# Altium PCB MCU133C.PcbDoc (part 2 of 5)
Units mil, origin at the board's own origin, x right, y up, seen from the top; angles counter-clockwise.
Board outline 2300 x 5500 mil, 4 copper layers (Top Signal, GND, PWR, Bottom Signal), stack 61.6 mil thick; 278 components, 226 nets, 1057 pads, 868 vias.
Unrouted connection lines stored in the file: 237.
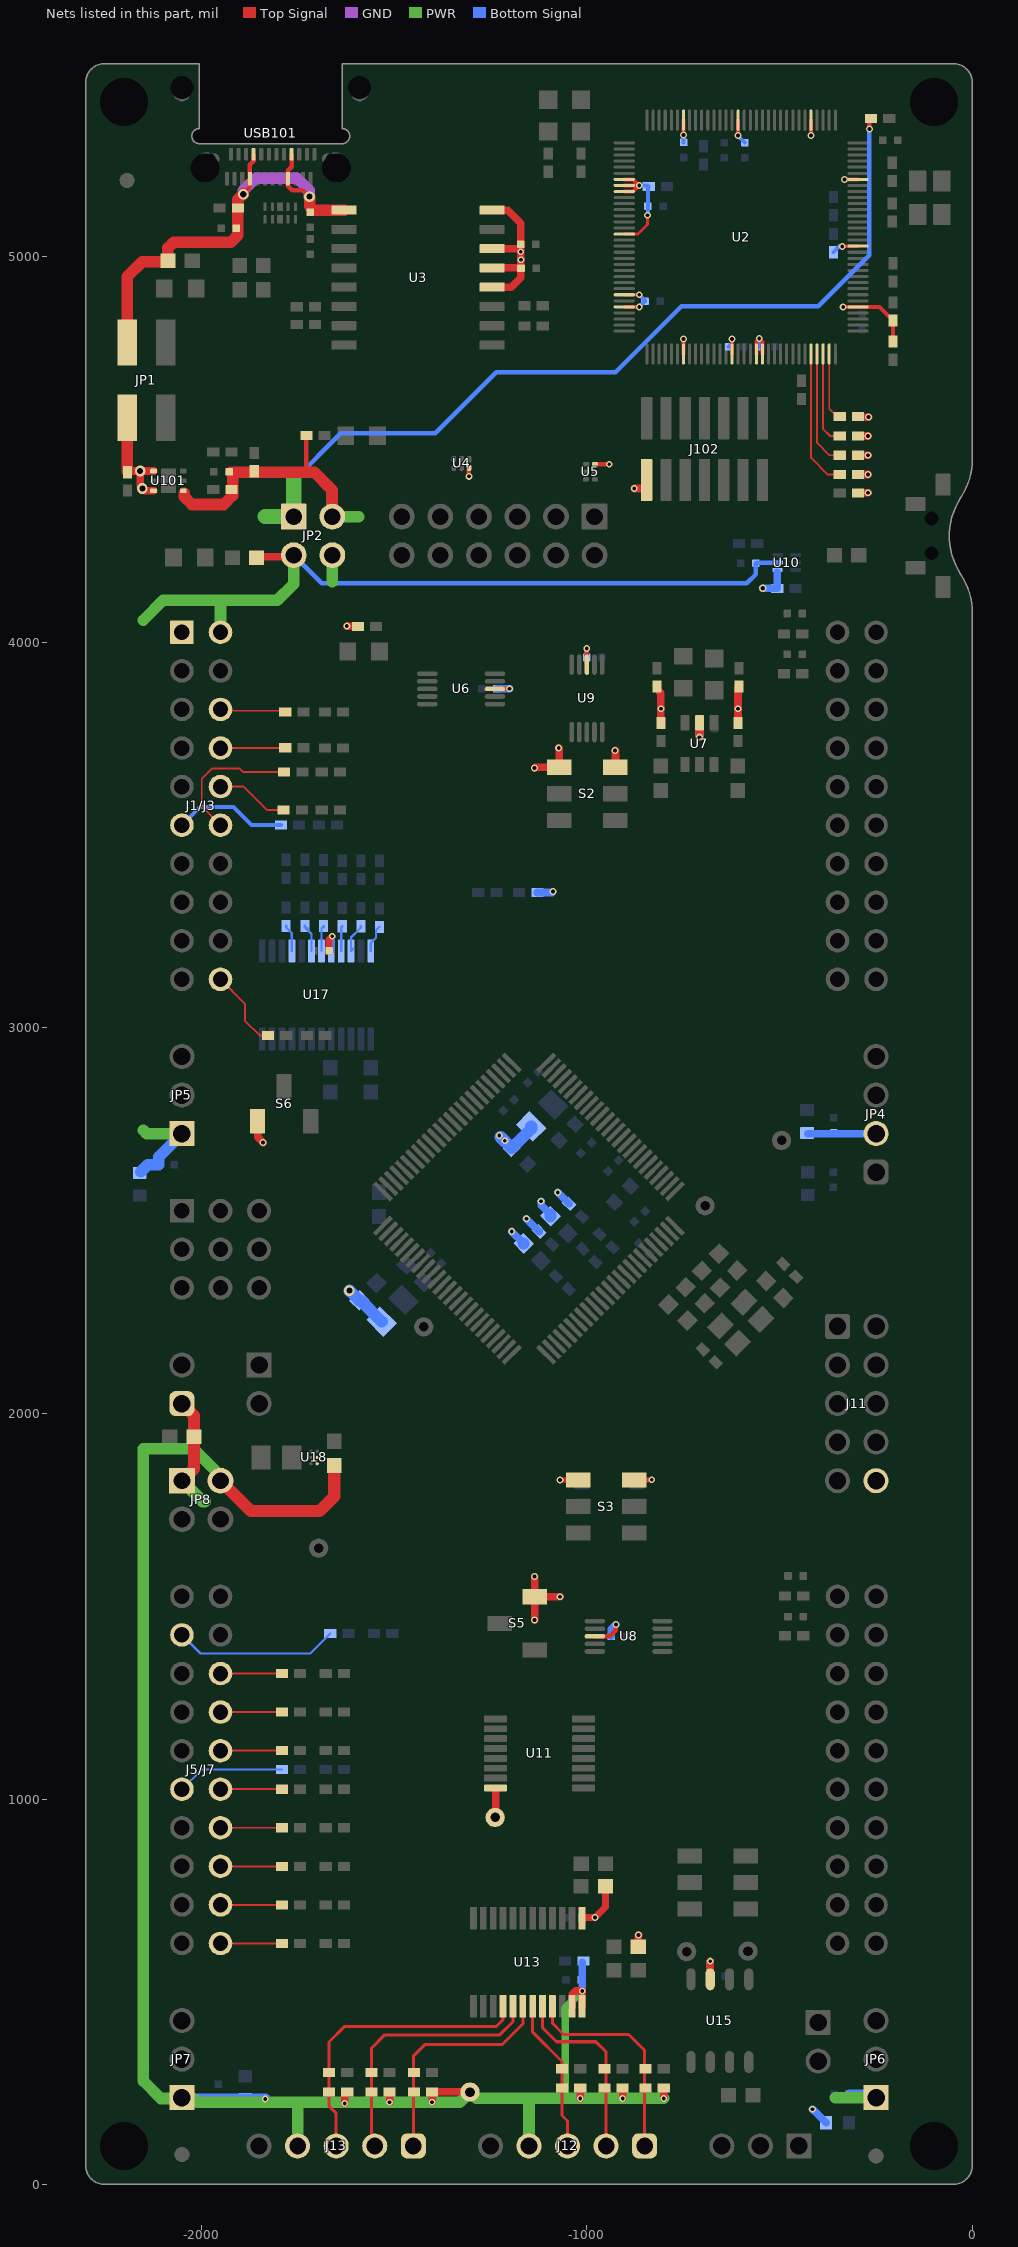
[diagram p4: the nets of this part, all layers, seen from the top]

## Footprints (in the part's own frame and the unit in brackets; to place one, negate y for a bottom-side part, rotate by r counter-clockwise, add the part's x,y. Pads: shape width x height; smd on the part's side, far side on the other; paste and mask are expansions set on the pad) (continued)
WL-SMCW_RED_0805 [mm] "SMD, 2-Leads, Body 1.6x0.8mm"
  rect 1.1x1.2 smd: 1(-1.05,0) 2(1.05,0)
  silkscreen extent -2.4,-1.1 1.5,1.1, body extent -1,-0.62 1,0.63, height 0.7
Wurth_60900213421 [mil] "Shunt, 2.54mm, Black"
  round 1 on Mech3: 0(0,0)
  body extent -98,-48 98,48, height 338
WURTH_61300211121#1 [mm] "Header, 2.54mm, 2x1, TH"
  rect 1.65x1.65 hole 1.15: 1(-1.27,0)
  round 1.65 hole 1.15: 2(1.27,0)
  silkscreen extent -2.54,-1.27 2.54,1.6, body extent -2.54,-1.27 2.54,1.27, height 8.54
WURTH_61300211121#2 [mm] "Header, 2.54mm, 2x1, TH"
  rrect50% 1.65x1.65 hole 1.15: 1(-1.27,0)
  round 1.65 hole 1.15: 2(1.27,0)
  body extent -2.54,-1.27 2.54,1.27, height 8.54
WURTH_61300311121 [mm] "Header, 2.54mm, 3x1, TH"
  rect 1.65x1.65 hole 1.15: 1(-2.54,0)
  round 1.65 hole 1.15: 2(0,0) 3(2.54,0)
  silkscreen extent -3.81,-1.65 3.81,1.27, body extent -3.81,-1.27 3.81,1.27, height 8.54
WURTH_61300411121 [mm] "Header, 2.54mm, 4x1, TH"
  rrect50% 1.65x1.65 hole 1.15: 1(-3.81,0)
  round 1.65 hole 1.15: 2(-1.27,0) 3(1.27,0) 4(3.81,0)
  body extent -5.08,-1.27 5.08,1.27, height 8.54
Wurth_61300511121 [mm] "Header, 2.54mm, 5x1, TH"
  rrect50% 1.65x1.65 hole 1.1: 1(-5.08,0)
  round 1.65 hole 1.1: 2(-2.54,0) 3(0,0) 4(2.54,0) 5(5.08,0)
  body extent -6.35,-1.27 6.35,1.27, height 8.54
WURTH_61301021121 [mm] "Header, 2.54mm, 5x2, TH"
  rrect25% 1.65x1.65 hole 1.15: 1(-5.08,-1.27)
  round 1.65 hole 1.15: 2(-5.08,1.27) 3(-2.54,-1.27) 4(-2.54,1.27) 5(0,-1.27) 6(0,1.27) 7(2.54,-1.27) 8(2.54,1.27) 9(5.08,-1.27) 10(5.08,1.27)
  silkscreen extent -6.35,-2.9 6.35,2.54, body extent -6.35,-2.54 6.35,2.54, height 8.54
YFF0006AEAE [mm] "DSBGA-6"
  round 0.23 smd paste-0.13 mask+0.038: A1(-0.2,0.4) A2(0.2,0.4) B1(-0.2,0) B2(0.2,0) C1(-0.2,-0.4) C2(0.2,-0.4)
  body extent -0.45,-0.65 0.45,0.65, height 0.63

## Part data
C1 C2 C10 C11 C12 C14 C20 C21 C22 C43 C44 C45 C46 C54 C55 C60 C64 C65 C66 C74 C81 C82 C83 C84 C105 C106: library part CMP-0090362-1, "0.1µF ±10% 10V Ceramic Capacitor X7R 0402 (1005 Metric)", Digikey Part Number=732-7513-1-ND, Manufacturer="Wurth Electronics", Mouser Part Number=710-885012205018, Operating Temperature Range="-55°C to +125°C", TempCo=15%, Temperature Characteristic=X7R, Tolerance_%=10%, ValueDisplayed=100000pF
C6 C7 C17: library part CMP-0006228-2, "CAP, CERM, 0.1 uF, 16 V, +/- 10%, X7R, 0402", Cap_Case=0402, Manufacturer="Wurth Elektronik", Supplier Part Number 1=732-7532-1-ND, TempCo=X7R, Tolerance_%=10%, Value1=Unknown, Value2=16V, ValueDisplayed=0.1uF
C9 C18 C19 C111 C113 C115 C117 C119: library part CMP-0092309-1, "Cap Ceramic 10uF 10V X5R 10% SMD 0603 85C Paper T/R", Digikey Part Number=311-1782-1-ND, Manufacturer=YAGEO, Mouser Part Number=603-CC603KRX5R6BB106, Octopart Part Number=1f0ad7d7c223c0cd, Operating Temperature Range="-55°C to +85°C", TempCo=15%, Temperature Characteristic=X5R, Tolerance_%=10%, ValueDisplayed=10uF
C15 C16 C24: library part CMP-0007091-1, "CAP, CERM, 2.2 uF, 10 V, +/- 10%, X5R, AEC-Q200 Grade 3, 0603", Cap_Case=0603, Manufacturer=TDK, Supplier Part Number 1=445-12444-1-ND, TempCo=X5R, Tolerance_%=10%, Value1=Unknown, Value2=10V, ValueDisplayed=2.2uF
C25 C26 C27 C28 C29 C30 C31 C32 C33 C34 C35 C36 C37 C38 C39 C40 C75 C76 C77 C78 C107 C108: library part CMP-0006456-2, "CAP, CERM, 330 pF, 50 V, +/- 5%, C0G/NP0, 0402", Cap_Case=0402, Manufacturer=MuRata, Supplier Part Number 1=490-1295-1-ND, TempCo=C0G/NP0, Tolerance_%=5%, Value1=Unknown, Value2=50V, ValueDisplayed=330pF
C41 C42: library part CMP-0006239-2, "CAP, CERM, 12 pF, 25 V, +/- 5%, C0G/NP0, AEC-Q200 Grade 1, 0402", Cap_Case=0402, Manufacturer=Kemet, Supplier Part Number 1=399-6829-1-ND, TempCo=C0G/NP0, Tolerance_%=5%, Value1=Unknown, Value2=25V, ValueDisplayed=12pF
C50 C51 C52 C53 C58 C102: library part CMP-0090363-1, "10000pF ±10% 25V Ceramic Capacitor X7R 0402 (1005 Metric)", Digikey Part Number=732-7545-1-ND, Manufacturer="Wurth Electronics", Mouser Part Number=710-885012205050, Operating Temperature Range="-55°C to +125°C", TempCo=15%, Temperature Characteristic=X7R, Tolerance_%=10%, ValueDisplayed=10000pF
C56 C57 C59 C61 C100 C103: library part CMP-0064924-2, "CAP, CERM, 1 uF, 10 V,+/- 20%, X5R, 0402", Cap_Case=0402, Manufacturer="Wurth Elektronik", Supplier Part Number 1=732-7489-1-ND, TempCo=X5R, Tolerance_%=20%, Value1=Unknown, Value2=10V, ValueDisplayed=1uF
C62 C63: library part CMP-0006345-2, "CAP, CERM, 12 pF, 50 V, +/- 5%, C0G/NP0, 0402", Cap_Case=0402, Manufacturer="Samsung Electro-Mechanics", Supplier Part Number 1=1276-1178-1-ND, TempCo=C0G/NP0, Tolerance_%=5%, Value1=Unknown, Value2=50V, ValueDisplayed=12pF
C67 C68 C69 C70 C71 C72 C73: library part CMP-0006231-2, "CAP, CERM, 1000 pF, 50 V, +/- 10%, X7R, 0402", Cap_Case=0402, Manufacturer="Wurth Elektronik", Supplier Part Number 1=732-7556-1-ND, TempCo=X7R, Tolerance_%=10%, Value1=Unknown, Value2=50V, ValueDisplayed=1000pF
C101: library part CMP-0092424-1, "Cap Cer 3300pF 50V X7R 0402", Digikey Part Number=732-7559-1-ND, Manufacturer="Wurth Electronics", Mouser Part Number=710-885012205064, Operating Temperature Range="-55°C to +125°C", TempCo=15%, Temperature Characteristic=X7R, Tolerance_%=10%, ValueDisplayed=3.3nF
C109: library part CMP-0006825-5, "CAP, CERM, 2.2 uF, 16 V, +/- 20%, X5R, 0603", Cap_Case=0603, Manufacturer="Wurth Elektronik", Supplier Part Number 1=732-7915-1-ND, TempCo=X5R, Tolerance_%=20%, Value1=Unknown, Value2=16V, ValueDisplayed=2.2uF
C110: library part CMP-0086225-1, "CAP, CERM, 10 µF, 16 V,+/- 10%, X5R, 0603", Cap_Case=0603, Manufacturer=MuRata, Supplier Part Number 1=490-10728-1-ND, TempCo=X5R, Tolerance_%=10%, Value2=16V, ValueDisplayed=10µF
C112 C114 C116 C118 C120 C121 C122: library part CMP-0090362-1, "0.1µF ±10% 10V Ceramic Capacitor X7R 0402 (1005 Metric)", Digikey Part Number=732-7513-1-ND, Manufacturer="Wurth Electronics", Mouser Part Number=710-885012205018, Operating Temperature Range="-55°C to +125°C", TempCo=15%, Temperature Characteristic=X7R, Tolerance_%=10%, ValueDisplayed=0.1uF
"CE Logo1": library part CMP-0074844-1
FID1 FID2 FID3 FID4 FID5 FID6: library part CMP-0077181-1, "Fiducial mark.  There is nothing to buy or mount.", Manufacturer=N/A
J1/J3: library part CMP-0003837-4, "Receptacle, 2.54mm, 10x2, Tin, TH", Alternate Manufacturer="Major League Electronics", Alternate PartNumber=CRD-081413-A-G, Manufacturer=Samtec, Supplier Part Number 1=SAM1204-10-ND
J4/J2: library part CMP-0078266-4, "Receptacle, 2.54mm, 10x2, Tin, TH", Alternate Manufacturer="Major League Electronics", Alternate PartNumber=CRD-081413-A-G, Manufacturer=Samtec, Supplier Part Number 1=SAM1204-10-ND
J5/J7: library part CMP-0081070-3, "Receptacle, 2.54mm, 10x2, Tin, TH", Alternate Manufacturer="Major League Electronics", Alternate PartNumber=CRD-081413-A-G, Manufacturer=Samtec, Supplier Part Number 1=SAM1204-10-ND
J8/J6: library part CMP-0081071-3, "Receptacle, 2.54mm, 10x2, Tin, TH", Alternate Manufacturer="Major League Electronics", Alternate PartNumber=CRD-081413-A-G, Manufacturer=Samtec, Supplier Part Number 1=SAM1204-10-ND
J10: library part CMP-0090263-1, Digikey Part Number=SAM10328-ND, Manufacturer=Samtec, Mouser Part Number=200-TSW10307GT, Operating Temperature Range="-55°C to +125°C"
J11: library part CMP-0054806-3, "Header, 2.54 mm, 5x2, Gold, TH", Current_A=3A, Manufacturer="Wurth Elektronik", Supplier Part Number 1=732-2672-ND, Voltage_V=250V
J12 J13: library part CMP-0084909-1, "Header, 2.54mm, 5x1, Gold, TH", Color=Black, Current_A=3A, Manufacturer="Wurth Elektronik", Voltage_V=250V
J14 JP5 JP6 JP7: library part CMP-0054796-1, "Header, 2.54 mm, 3x1, Gold, TH", Manufacturer="Wurth Elektronik", Supplier Part Number 1=732-5316-ND
J15 JP9: library part CMP-0054794-1, "Header, 2.54 mm, 2x1, Gold, TH", Manufacturer="Wurth Elektronik", Supplier Part Number 1=732-5315-ND
J16: library part CMP-0054794-2, "Header, 2.54 mm, 2x1, Gold, TH", Color=Black, Manufacturer="Wurth Elektronik", Supplier Part Number 1=732-5315-ND
J101: library part CMP-0092423-1, "THT Vertical Pin Header WR-PHD, Pitch 2.54 mm, Dual Row, 12 pins", Current_A=3A, Digikey Part Number=732-5297-ND, Manufacturer="Wurth Electronics", Mouser Part Number=710-61301221121, Operating Temperature Range="-40°C to +105°C", Voltage_V=250V
J102: library part CMP-0092335-1, "Connector, Header, Dual Row, 14 pin, .05\" pitch/row spacing, Male, Shrouded, Keyed, IDC, SMT", Current_A=3.4A, Digikey Part Number=612-FTSH-107-01-F-DV-K-ND, Manufacturer=Samtec, Mouser Part Number=200-FTSH10701FDVK, Octopart Part Number=b9dd70752dfc661a, Operating Temperature Range="-55°C to +125°C"
JP1: library part CMP-0055559-1, "Header, 2.54mm, 2x2, Gold, SMT", Color=Black, Manufacturer=Samtec, Supplier Part Number 1=TSM-102-01-L-DV-ND, Voltage_V=475V
JP2 JP8: library part CMP-0092422-1, "THT Vertical Pin Header WR-PHD, Pitch 2.54 mm, Dual Row, 4 pins", Current_A=3A, Digikey Part Number=732-5294-ND, Manufacturer="Wurth Electronics", Mouser Part Number=710-61300421121, Operating Temperature Range="-40°C to +105°C", Voltage_V=250V
JP4: library part CMP-0054798-2, "Header, 2.54 mm, 4x1, Gold, TH", Color=Black, Manufacturer="Wurth Elektronik", Supplier Part Number 1=732-5317-ND
L2: library part CMP-0003093-1, "Ferrite Bead, 60 ohm @ 100 MHz, 3 A, 0805", Manufacturer="Wurth Elektronik", Supplier Part Number 1=732-1612-1-ND, Value1="0.025 ohm", Value2=3A, ValueDisplayed="60 ohm"
L3: library part CMP-0003073-1, "Ferrite Bead, 220 ohm @ 100 MHz, 2 A, 0805", Manufacturer="Wurth Elektronik", Supplier Part Number 1=732-1614-1-ND, Value1="0.05 ohm", Value2=2A, ValueDisplayed="220 ohm"
L4: library part CMP-0058739-1, "Inductor, Multilayer, Ferrite, 1 uH, 0.8 A, 0.19 ohm, SMD", Manufacturer=MuRata, Supplier Part Number 1=490-4992-1-ND, Value1="0.19 ohm", Value2=0.8A, ValueDisplayed=1uH
LED0 LED1 LED4 LED6 LED7: library part CMP-0002951-3, "LED, Red, SMD", Color=Red, Manufacturer="Wurth Elektronik", Power_TotalModule=72mW, Value1=0.072W, Value2=1.9V
LED2 LED3: library part CMP-0002889-2, "LED, Blue, SMD", Color=Blue, Manufacturer=Lite-On, Value1=W, Value2=3.3V
LED5: library part CMP-0002830-3, "LED, Green, SMD", Color=green, Manufacturer=Lite-On, Value1=W, Value2=2.1V
Logo1 Logo5: library part CMP-0074838-1, "Texas Instrument Corporate Signature"
Logo3: library part CMP-0074847-1, "FCC_disclaimer"
Logo4: library part CMP-0074769-1
M1 M2 M3 M4 M5 M6 M7 M8 M9 M10 M11 M12 M13: library part CMP-0003761-2, "Shunt, 2.54mm, Gold, Black", Manufacturer="Wurth Elektronik", Supplier Part Number 1=732-2678-ND
MH1 MH2 MH3 MH4: library part CMP-0078424-2, "PCB Mounting Hole, No Pad", Manufacturer=Any, PartNumber=N/A
R1 R2 R8 R9 R12 R13 R14 R15 R16 R17 R18 R19 R20 R21 R22 R23 R24 R25 R26 R27 R44 R45 R49 R50 R84 R85 R86 R87 R103 R104 R109 R110: library part CMP-0027004-2, "RES, 0, 5%, 0.063 W, 0402", Manufacturer="Yageo America", Power_W=63mW, Supplier Part Number 1=311-0.0JRCT-ND, TempCo="200 ppm/C", Tolerance_%=5%, Value2=0.063W, Value_Code=0000, ValueDisplayed=0
R3 R28 R29 R105: library part CMP-0026962-3, "RES, 680, 5%, 0.063 W, AEC-Q200 Grade 0, 0402", Manufacturer=Vishay-Dale, Power_W=63mW, Supplier Part Number 1=541-680JCT-ND, TempCo="200 ppm/C", Tolerance_%=5%, Value2=0.063W, Value_Code=680R, ValueDisplayed=680
R5: library part CMP-0025874-4, "RES, 0, 5%, 0.1 W, AEC-Q200 Grade 0, 0603", Manufacturer=Panasonic, Power_W=100mW, Supplier Part Number 1=P0.0GCT-ND, TempCo="600 ppm/C", Tolerance_%=5%, Value2=0.1W, Value_Code=0000, ValueDisplayed=0
R7 R43: library part CMP-0025921-5, "RES, 3.0 k, 5%, 0.1 W, 0603", Manufacturer=Yageo, Power_W=100mW, Supplier Part Number 1=311-3.0KGRCT-ND, TempCo="100 ppm/C", Tolerance_%=5%, Value2=0.1W, Value_Code=3k00, ValueDisplayed=3.0k
R10 R11: library part CMP-0026890-5, "RES, 2.2 k, 5%, 0.063 W, AEC-Q200 Grade 0, 0402", Manufacturer=Vishay-Dale, Power_W=63mW, Supplier Part Number 1=541-2.2KJCT-ND, TempCo="200 ppm/C", Tolerance_%=5%, Value2=0.063W, Value_Code=2k20, ValueDisplayed=2.2k
R30 R31: library part CMP-0026826-2, "RES, 10 M, 5%, 0.063 W, AEC-Q200 Grade 0, 0402", Manufacturer=Vishay-Dale, Power_W=63mW, Supplier Part Number 1=541-10MJCT-ND, TempCo="200 ppm/C", Tolerance_%=5%, Value2=0.063W, Value_Code=10M0, ValueDisplayed=10M
R32 R33 R34 R35 R36 R37 R47 R52 R53 R107 R108: library part CMP-0025697-4, "RES, 0, 5%, 0.1 W, AEC-Q200 Grade 0, 0603", Manufacturer=Vishay-Dale, Power_W=100mW, Supplier Part Number 1=541-0.0GCT-ND, TempCo="200 ppm/C", Tolerance_%=5%, Value2=0.1W, Value_Code=0000, ValueDisplayed=0
R38 R39 R111 R112: library part CMP-0022746-5, "RES, 10.0 k, 1%, 0.1 W, 0603", Manufacturer=Yageo, Power_W=100mW, Supplier Part Number 1=311-10.0KHRCT-ND, TempCo="100 ppm/C", Tolerance_%=1%, Value2=0.1W, Value_Code=10k0, ValueDisplayed=10.0k
R48: library part CMP-0025769-4, "RES, 2.2 k, 5%, 0.1 W, AEC-Q200 Grade 0, 0603", Manufacturer=Vishay-Dale, Power_W=100mW, Supplier Part Number 1=541-2.2KGCT-ND, TempCo="200 ppm/C", Tolerance_%=5%, Value2=0.1W, Value_Code=2k20, ValueDisplayed=2.2k
R57: library part CMP-0026918-5, "RES, 3.3 k, 5%, 0.063 W, AEC-Q200 Grade 0, 0402", Manufacturer=Vishay-Dale, Power_W=63mW, Supplier Part Number 1=541-3.3KJCT-ND, TempCo="200 ppm/C", Tolerance_%=5%, Value2=0.063W, Value_Code=3k30, ValueDisplayed=3.3k
R58 R59 R60 R61 R72 R73 R74 R75 R76 R77: library part CMP-0026071-3, "RES, 1.00 k, 1%, 0.063 W, AEC-Q200 Grade 0, 0402", Manufacturer=Vishay-Dale, Power_W=63mW, Supplier Part Number 1=541-1.00KLCT-ND, TempCo="100 ppm/C", Tolerance_%=1%, Value2=0.063W, Value_Code=1k00, ValueDisplayed=1.00k
R62: library part CMP-0026824-3, "RES, 100, 5%, 0.063 W, AEC-Q200 Grade 0, 0402", Manufacturer=Vishay-Dale, Power_W=63mW, Supplier Part Number 1=541-100JCT-ND, TempCo="200 ppm/C", Tolerance_%=5%, Value2=0.063W, Value_Code=100R, ValueDisplayed=100
R63 R64: library part CMP-0026736-1, "RES, 470, 1%, 0.063 W, 0402", Manufacturer="Yageo America", Power_W=63mW, Supplier Part Number 1=311-470LRCT-ND, TempCo="100 ppm/C", Tolerance_%=1%, Value2=0.063W, Value_Code=470R, ValueDisplayed=470
R65 R67: library part CMP-0026825-5, "RES, 10 k, 5%, 0.063 W, AEC-Q200 Grade 0, 0402", Manufacturer=Vishay-Dale, Power_W=63mW, Supplier Part Number 1=541-10KJCT-ND, TempCo="200 ppm/C", Tolerance_%=5%, Value2=0.063W, Value_Code=10k0, ValueDisplayed=10k
R68: library part CMP-0026413-2, "RES, 4.87 k, 1%, 0.063 W, AEC-Q200 Grade 0, 0402", Manufacturer=Vishay-Dale, Power_W=63mW, Supplier Part Number 1=541-4.87KLCT-ND, TempCo="100 ppm/C", Tolerance_%=1%, Value2=0.063W, Value_Code=4k87, ValueDisplayed=4.87k
R70: library part CMP-0026946-3, "RES, 51, 5%, 0.063 W, AEC-Q200 Grade 0, 0402", Manufacturer=Vishay-Dale, Power_W=63mW, Supplier Part Number 1=541-51JCT-ND, TempCo="200 ppm/C", Tolerance_%=5%, Value2=0.063W, Value_Code=51R0, ValueDisplayed=51
R79: library part CMP-0022769-3, "RES, 120, 1%, 0.1 W, 0603", Manufacturer="Yageo America", Power_W=100mW, Supplier Part Number 1=311-120HRCT-ND, TempCo="200 ppm/C", Tolerance_%=1%, Value2=0.1W, Value_Code=120R
R82 R83: library part CMP-0026992-3, "RES, 0, 5%, 0.1 W, AEC-Q200 Grade 0, 0402", Manufacturer=Panasonic, Power_W=100mW, Supplier Part Number 1=P0.0JCT-ND, TempCo="600 ppm/C", Tolerance_%=5%, Value2=0.1W, Value_Code=0000, ValueDisplayed=0
R88 R89: library part CMP-0025932-5, "RES, 5.1 k, 5%, 0.1 W, 0603", Manufacturer=Yageo, Power_W=100mW, Supplier Part Number 1=311-5.1KGRCT-ND, TempCo="100 ppm/C", Tolerance_%=5%, Value2=0.1W, Value_Code=5k10, ValueDisplayed=5.1k
R100: library part CMP-0026100-2, "RES, 1.00 M, 1%, 0.063 W, AEC-Q200 Grade 0, 0402", Manufacturer=Vishay-Dale, Power_W=63mW, Supplier Part Number 1=541-1.00MLCT-ND, TempCo="100 ppm/C", Tolerance_%=1%, Value2=0.063W, Value_Code=1M00, ValueDisplayed=1.00M
R101: library part CMP-0026441-2, "RES, 52.3 k, 1%, 0.063 W, AEC-Q200 Grade 0, 0402", Manufacturer=Vishay-Dale, Power_W=63mW, Supplier Part Number 1=541-52.3KLCT-ND, TempCo="100 ppm/C", Tolerance_%=1%, Value2=0.063W, Value_Code=52k3, ValueDisplayed=52.3k
R102: library part CMP-0078244-2, "RES, 30.0 k, 1%, 0.063 W, AEC-Q200 Grade 0, 0402", Manufacturer=Vishay-Dale, Power_W=63mW, Supplier Part Number 1=541-30.0KLCT-ND, TempCo="100 ppm/C", Tolerance_%=1%, Value2=0.063W, Value_Code=30k0, ValueDisplayed=30.0k
R106: library part CMP-0023387-3, "RES, 50, 0.1%, 0.125 W, 0603", Manufacturer="Vishay Thin Film", Power_W=125mW, Supplier Part Number 1=FC0603-50BFCT-ND, TempCo="25 ppm/C", Tolerance_%=0.1%, Value2=0.125W, Value_Code=50R0, ValueDisplayed=50
S1: library part CMP-0002328-1, "Switch, SPST, 0.05 A, 12 VDC, SMD", CurrentRating_mA=50A, Manufacturer=Diptronics
S2 S3: library part CMP-0002233-1, "Switch, Dual SPDT,  2 Pos, 0.1A, 6VDC, SMD", CurrentRating_mA=100A, Manufacturer="Copal Electronics", Supplier Part Number 1=CASD20JCT-ND
S4: library part CMP-0002123-2, "SLIDE SWITCH DPDT  .1A, SMT", CurrentRating_mA=100A, Manufacturer="Copal Electronics", Supplier Part Number 1=CAS220JCT-ND
S5 S6: library part CMP-0002139-2, "Switch, Slide, SPDT  100mA, SMT", CurrentRating_mA=100A, Manufacturer="Copal Electronics", Supplier Part Number 1=CAS120JCT-ND
TP1 TP2 TP3 TP4 TP5 TP6 TP7 TP8: library part CMP-0078143-3, "TEST POINT.  No entry in BOM.", Manufacturer=N/A
U1: library part CMP-0043282-2, "Real-Time Microcontroller, LQFP100", Frequency_Fixed=150MHz, Manufacturer="Texas Instruments", Max Supply Voltage=3.63V, Min Supply Voltage=2.8V, Operating Temperature Range="-40°C to +150°C"
U2: library part CMP-0077953-1, "MSP432E401YTPDT, PDT0128A (TQFP-128)", Alternate Manufacturer="Texas Instruments", Alternate PartNumber=MSP432E401YTPDTR
U3: library part CMP-0091303-1, "Full/Low Speed Isolated USB Repeater, SOIC16-Wide", Manufacturer="Texas Instruments", Max Supply Voltage=5.5V, Min Supply Voltage=3V, Nominal Supply Current=9-9.5mA, Operating Temperature Range="-55°C to +150°C"
U4 U5: library part CMP-0043115-3, "4-Channel ESD Protection Array for High-Speed Data Interfaces, DRY0006A (USON-6)", Breakdown Voltage(Min)(V)=6, IO Capacitance(Typ)(pF)=1.6, IO Leakage Current(nA)=1, Manufacturer="Texas Instruments", Operating Temperature Range="-40 to 85 C", Rating=Catalog
U6 U8 U9: library part CMP-0067418-1, "DUAL 10-Ohm SPDT ANALOG SWITCH, DGS0010A (VSSOP-10)", Alternate Manufacturer="Texas Instruments", Alternate PartNumber=TS5A23157DGST
U7: library part CMP-0051789-2, "Dual Buffer/Driver with Open-Drain Output, DBV0006A, LARGE T&R", F @ Nom Voltage(Max)(Mhz)=150, Generic Part Number=SN74LVC2G07, ICC @ Nom Voltage(Max)(mA)=0.01, Manufacturer="Texas Instruments", Operating Temperature Range(C)="-40 to 125", Rating=Catalog, tpd @ Nom Voltage(Max)(ns)=8.6,4.4,3.7,2.9, Voltage(Nom)(V)=1.8,2.5,3.3,5
U10: library part CMP-0750051-1, "Overvoltage and Undervoltage Reset IC With Time Delay and Manual Reset, DSE0006A (WSON-6)", Alternate Manufacturer="Texas Instruments"
U11: library part CMP-0089841-1, "3 Circuit IC Switch 2:1 75Ohm 16-TSSOP", Digikey Part Number=296-3833-1-ND, Manufacturer="Texas Instruments", Max Supply Voltage=5.5V, Min Supply Voltage=2V, Mouser Part Number=595-SN74LV4053APWR, Nominal Supply Current=20uA, On State Resistance=100-225Ω, Operating Temperature Range="-40°C to +85°C"
U13: library part CMP-0121414-1, "8-Bit Dual-Supply Bus Transceiver With Configurable Voltage Translation and 3-State Outputs", Digikey Part Number=296-34079-5-ND, Manufacturer="Texas Instruments", Mouser Part Number=595-SN74LVC8T245PWR, Nominal Supply Current=25uA, Operating Temperature Range="-40°C to +85°C"
U15: library part CMP-0080978-2, "3.3-V CAN Transceivers with CAN FD (Flexible Data Rate), D0008A (SOIC-8)", Alternate Manufacturer="Texas Instruments", Alternate PartNumber=TCAN332GD
U16: library part CMP-0073613-3, "4-Channel Ultra-Low-Capacitance IEC ESD Protection Diode, DQA0010A (USON-10)", Alternate Manufacturer="Texas Instruments"
U17: library part CMP-0092155-1, "3.3-V, 2:1 (SPDT), 6-channel analog multiplexer with 1.8-V compatible control inputs 24-TSSOP -40 to 85", Digikey Part Number=296-24570-1-ND, Manufacturer="Texas Instruments", Max Supply Voltage=3.6V, Min Supply Voltage=1.65V, Mouser Part Number=595-TS3A27518EPWR, Nominal Supply Current=0.01-0.04uA, Octopart Part Number=cf0206a9c1b910c5, On State Resistance=4.4Ω, Operating Temperature Range="-40°C to +85°C"
U18: library part CMP-0067212-2, "5V, 500mA, 4MHz Step-Up DC/DC Converter, YFF0006AEAE (DSBGA-6)", Alternate Manufacturer="Texas Instruments", Alternate PartNumber=TPS61241YFFT, Operating Temperature Range="-40 to 85 C", Rating=Catalog
U101: library part CMP-0066914-5, "1% High-Accuracy, 1-A, Low-Dropout Regulator with Reverse Current Protection, DRV0006A (WSON-6)", Alternate Manufacturer="Texas Instruments", Alternate PartNumber=TPS7A3701DRVT
USB101: library part CMP-0092137-1, "Connector, USB Type-C 24 pin Mid Mount dual row Receptacle Surface Mount", Manufacturer=MUP, Operating Temperature Range="-25°C to +85°C"
Y1: library part CMP-0094478-1, "Crystal 16 MHz ±20ppm Crystal 8pF 70 Ohms 4-SMD, No Lead", Digikey Part Number=732-830064296CT-ND, Frequency Stability=20ppm, Frequency_Fixed=16MHz, Load Capacitance=8pF, Manufacturer=Wurth, Mouser Part Number=710-830064296, Operating Temperature Range="-10°C to +70°C"
Y2: library part CMP-0093781-1, "20 MHz ±10ppm Crystal 8pF 50 Ohms 4-SMD, No Lead", Digikey Part Number=1923-830108207209CT-ND, Frequency Stability=20ppm, Frequency Tolerance=10ppm, Frequency_Fixed=20MHz, Load Capacitance=8pF, Manufacturer="Wurth Electronics", Mouser Part Number=710-830108207209, Operating Temperature Range="-40°C to +85°C"
ZZ1: library part CMP-0077236-1
ZZ2: library part CMP-0077237-1
ZZ3: library part CMP-0077238-1

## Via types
v1: diameter 17.72, hole 9.84, Top Signal to Bottom Signal, tented both sides, 822 vias
v2: diameter 19.68, hole 11.81, Top Signal to Bottom Signal, tented both sides, 22 vias
v3: diameter 27.56, hole 15.75, Top Signal to Bottom Signal, tented both sides, 17 vias
v4: diameter 15.75, hole 7.87, Top Signal to Bottom Signal, tented both sides, 5 vias
v5: diameter 19.68, hole 7.87, Top Signal to Bottom Signal, tented both sides, 2 vias

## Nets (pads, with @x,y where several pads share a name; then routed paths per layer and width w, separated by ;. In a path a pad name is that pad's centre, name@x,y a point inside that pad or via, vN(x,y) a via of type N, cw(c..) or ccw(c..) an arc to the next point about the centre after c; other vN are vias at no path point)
+3V3_MCU: C6.1 C16.1 C18.2 C43.1 C44.2 C45.1 C46.2 C64.1 C74.1 C109.1 C113.2 C114.1 C117.2 C118.1 C121.1 J1/J3.1 J11.10 J16.1 JP2.4 JP4.2 JP6.1 JP8.1 L2.1 L3.1 R3.2 R10.2 R11.2 R28.2 R29.2 R30.2 R31.2 R47.2 R48.2 R82.1 R111.2 R112.2 S2.1 S2.4 S3.3 S3.6 S5.3 S6.1 TP4.1 U6.8 U7.5 U8.8 U9.8 U10.1 U11.16 U13.1 U15.3 U17.8 | length 2760.9
  Top Signal w11.81: U6.8@-1238.35,3878.86 -1237.87,3879.33 v1(-1200.35,3879.33) ; v1(-1069.44,1827.4) S3.6@-1022.6,1827.4 ; U9.8@-1000.39,3946.42 v1(-1000.39,3983.94) ; U9.8@-999.93,3941.88 -999.93,3969.47 ; U8.8@-979.15,1422.07 -940.42,1422.07 -924.74,1437.75 v1(-924.74,1452.3) ; S3.3@-876.93,1827.4 -832.21,1827.4 v1(-831.74,1827.87)
  Top Signal w17.72: C121.1@-1668.53,3199.32 -1668.53,3229.06 v1(-1660.04,3237.55) ; U13.1@-1012.56,692.99 v1(-978.89,692.99) -951.93,719.96 R47.2@-951.93,774.29
  Top Signal w19.68: S6.1@-1853.94,2758.01 -1853.94,2716.85 v1(-1839.51,2702.42) ; JP2.4@-1660.04,4225.55 JP2.4@-1658.78,4224.29 ; v1(-1622.4,4041.57) R3.2@-1599.37,4041.57 ; TP4.1@-1237.05,975.35 -1236.75,975.65 U11.16@-1236.75,1020.87 ; v1(-1135.52,3673.55) -1133.52,3675.55 S2.1@-1072.03,3675.55 ; v1(-1135.43,1464.3) S5.3@-1135.43,1524.5 ; v1@-1135.43,1576.57 S5.3@-1135.43,1524.5 ; v1(-1073.11,3725.55) -1071.81,3724.25 S2.1@-1071.81,3675.77 ; v1@-1069.21,1524.5 S5.3@-1135.43,1524.5 ; v1(-926.77,3719.42) -925.67,3718.32 S2.4@-925.67,3676.24 ; R48.2@-866.79,616.5 -866.79,646.79 v1(-866.1,647.48) ; R28.2@-819.25,3879.41 -808,3868.16 R30.2@-808,3790.7 ; v1(-708,3753.69) U7.5@-708,3791.21 ; U15.3@-680.16,532.64 U15.3@-680.04,532.52 ; U15.3@-679.93,532.86 v1(-679.93,579.2) ; R31.2@-608,3790.7 R29.2@-608,3883.7
  Top Signal w31.5: JP8.1@-2050.04,1825.55 -2018.7,1856.89 C109.1@-2018.7,1939.12 -2018.7,1994.21 J16.1@-2050.04,2025.55
  PWR w30: -1660.04,4157.24 JP2.4@-1660.04,4225.55 ; -355.91,225.55 JP6.1@-250.04,225.55
  PWR w31.5: JP8.1@-2050.04,1825.55 -1995.94,1771.46 -1990.85,1771.46
  Bottom Signal w10: U17.8@-1663.73,3200.43 U17.8@-1662.62,3199.32 ; v1@-1660.04,3237.35 v1(-1660.04,3237.55)
  Bottom Signal w11.81: v1(-1000.39,3983.94) -1000.28,3983.82 C46.2@-1000.28,3960.28
  Bottom Signal w17.72: U17.8@-1662.62,3199.32 -1662.62,3234.77 v1@-1660.04,3237.35 ; C64.1@-1011.81,692.05 -979.84,692.05 v1(-978.89,692.99)
  Bottom Signal w19.68: C43.1@-1233.7,3879.33 v1(-1200.35,3879.33) ; v1(-1194.66,2471.7) R112.2@-1163.88,2440.91 ; v1(-1156.83,2504.65) R10.2@-1123.9,2471.7 ; R11.2@-1128.35,3350.95 -1090.43,3350.95 v1(-1088.15,3353.24) ; v1(-1118.68,2550.27) -1118.68,2540.31 R111.2@-1094.02,2515.66 ; v1(-1075.63,2573.19) -1075.53,2573.19 R82.1@-1045.97,2543.63 ; C45.1@-936.46,1422.07 -936.46,1440.58 v1(-924.74,1452.3) ; v1(-708,3753.69) C44.2@-708,3774.77 ; v1(-679.93,579.2) -679.72,578.99 C74.1@-679.72,540.88 ; v2(-544.29,4139.55) C6.1@-506.38,4139.55 ; C6.1@-506.15,4139.78 -506.15,4181.55 ; C113.2@-427.07,2725.55 JP4.2@-250.04,2725.55 JP4.2@-255.04,2720.55 ; v1(-415,195.73) -414.74,195.73 C117.2@-379.57,160.55
  Bottom Signal w23.62: C118.1@-319.33,234.55 -259.04,234.55 JP6.1@-250.04,225.55
  Bottom Signal w31.5: v3@-1615.11,2318.22 C16.1@-1590.15,2293.26 -1587.23,2293.26 L2.1@-1531.95,2237.98 ; v1@-1223.68,2716.97 C18.2@-1194.66,2687.96 -1144.32,2738.3 L3.1@-1144.32,2744.27 ; R112.2@-1163.88,2440.47 R112.2@-1163.88,2440.91 ; R111.2@-1094.02,2511.48 R111.2@-1094.02,2515.66
  other v1: -1069.44,1524.5 -1135.83,1577.36 -1212.7,2707.18 -1227.32,2720.65 -808.11,3827.42 -608.11,3827.42
  other v3: -1616.04,2318.55
+3V3_XDS110: C1.2 C2.2 C51.2 C52.2 C53.2 C54.2 C55.2 C56.1 C57.1 C58.2 C102.2 C103.1 J102.1 JP2.3 R57.2 R58.2 R59.2 R60.2 R61.2 R65.2 R70.2 R101.2 R105.2 U2.7 U2.8 U2.9 U2.16 U2.26 U2.28 U2.39 U2.47 U2.51 U2.52 U2.69 U2.79 U2.90 U2.101 U2.113 U2.122 U3.12 U3.13 U3.14 U3.16 U4.6 U5.6 U101.1 | length 2627.8
  Top Signal w7.87: U2.16@-902.99,5058.43 -867.56,5058.43 -842.64,5083.35 v1(-842.64,5107.2)
  Top Signal w10: U2.28@-902.99,4869.45 v1(-864.33,4869.45) ; U2.26@-902.99,4900.94 v1(-864.33,4900.94) ; U2.9@-902.99,5168.66 -880.08,5168.66 v1(-864.33,5184.41) ; U2.8@-902.99,5184.41 v1(-864.33,5184.41) ; U2.7@-902.99,5200.16 -880.08,5200.16 v1(-864.33,5184.41) ; U2.39@-749.45,4747.4 v1(-749.45,4786.06) ; v1(-749.45,5315.04) U2.122@-749.45,5353.7 ; U2.47@-623.46,4747.4 v1(-623.46,4786.06) ; v1(-607.72,5313.77) U2.113@-607.72,5353.7 ; U2.51@-560.47,4747.4 -560.47,4779.57 v1(-552.83,4787.2) -544.72,4779.09 U2.52@-544.72,4747.4 ; v1(-418.74,5313.77) U2.101@-418.74,5353.7 ; v1@-336.73,5026.65 U2.79@-296.46,5026.65 ; v1(-335.35,4869.45) U2.69@-296.69,4869.45 -241.46,4869.45 R65.2@-206.02,4834.02 ; v1(-331.77,5200.16) U2.90@-296.69,5200.16 ; R70.2@-206.38,4779.76 -206.38,4833.66 R65.2@-206.02,4834.02 ; R65.2@-203.35,4836.69 R65.2@-206.02,4834.02
  Top Signal w11.81: -1727.28,4445.79 R105.2@-1727.28,4535.55 ; v1(-1305.75,4430.04) -1305.75,4451.46 U4.6@-1305.28,4451.93 ; U5.6@-979.13,4461.42 v1(-942.07,4461.42)
  Top Signal w19.68: U3.12@-1245.67,4920.55 -1195.55,4920.55 -1171.46,4944.65 C2.2@-1171.46,4970.55 ; U3.13@-1245.67,4970.55 C2.2@-1171.46,4970.55 ; U3.14@-1245.67,5020.55 v1@-1174.8,5020.55 ; U3.16@-1245.67,5120.55 -1205.31,5120.55 -1171.46,5086.69 -1171.46,5021.38 -1171.46,4997.17 C2.2@-1171.46,4970.55 ; C2.2@-1170.71,4969.92 -1171.34,4970.55 C2.2@-1171.46,4970.55 ; v1(-876.93,4398.44) -851.99,4398.44 -844.84,4405.59 J102.1@-844.84,4420.43
  Top Signal w20: R57.2@-297.13,4387.48 R57.2@-296.97,4387.32 v1(-270.79,4387.32) ; R61.2@-297.13,4434.72 v1(-270.94,4434.72) ; R60.2@-297.13,4484.72 v1(-270.94,4484.72) ; R59.2@-297.13,4534.72 v1(-270.94,4534.72) ; R58.2@-295.98,4583.58 v1(-269.8,4583.58)
  Top Signal w30: -2044.37,4386.42 -2044.37,4377.44 -2023.98,4357.05 -1941.93,4357.05 -1918.82,4380.16 C102.2@-1918.82,4440.63 ; C102.2@-1922.99,4441.18 -1707.01,4441.18 -1660.04,4394.21 JP2.3@-1660.04,4325.55
  PWR w30: JP2.3@-1660.04,4311.34 JP2.3@-1660.04,4325.55 ; -1660.04,4387.64 JP2.3@-1660.04,4325.55 ; -1591.93,4325.55 JP2.3@-1660.04,4325.55
  Bottom Signal w10: v1(-864.33,4869.45) -850.12,4883.66 C55.2@-849.29,4883.66 -849.29,4885.91 v1(-864.33,4900.94) ; v1(-864.33,5184.41) -842.13,5184.41 C57.1@-839.68,5181.97 -841.34,5180.32 -841.34,5140.63 -841.34,5106.61 -841.93,5107.2 v1(-842.64,5107.2) ; v1(-749.45,5315.04) -749.45,5296.34 C52.2@-749.25,5296.14 ; C54.2@-632.36,4765.83 -623.46,4774.72 v1(-623.46,4786.06) ; v1(-607.72,5313.77) -607.72,5312.91 C51.2@-590.04,5295.24 ; C56.1@-360.83,5011.06 -344.96,5026.93 -344.06,5026.02 v1(-337.87,5026.02)
  Bottom Signal w11.81: C53.2@-554.45,4765.83 -552.83,4767.44 v1(-552.83,4787.2)
  other v1: -1171.04,4991.55 -1171.34,5012.55
+5V0_MCU: C65.2 C67.1 C110.1 C115.2 C116.1 C119.2 C120.1 C122.1 J1/J3.21 J12.4 J13.4 JP2.2 JP5.1 JP7.1 JP8.2 R43.2 R72.2 R73.2 R74.2 R75.2 R76.2 R77.2 TP5.1 U10.2 U13.23 U13.24 U18.B2 U18.C2 | length 7154.3
  Top Signal w12: U13.24@-1012.56,460.71 U13.24@-1012.13,461.14
  Top Signal w19.68: R43.2@-1856.3,4221.3 -1764.29,4221.3 JP2.2@-1760.04,4225.55 ; v1(-1627.72,210.63) R77.2@-1627.72,237.36 ; v1(-1511.42,213.82) R76.2@-1511.42,240.55 ; v1(-1401.42,213.82) R75.2@-1401.42,240.55 -1303.43,240.55 TP5.1@-1303.03,240.16 ; U13.23@-1038.04,460.71 -1038.04,493.65 -1029.25,502.44 v1(-1012.13,502.44) U13.24@-1012.13,461.14 ; R74.2@-1017.17,250.55 -1016.93,250.32 v1(-1016.93,223.58) ; v1(-907.17,223.82) R73.2@-907.17,250.55 ; v1(-800.43,223.82) R72.2@-800.43,250.55
  Top Signal w31.5: JP8.2@-1950.04,1825.55 -1871.04,1746.55 -1693.19,1746.55 -1655.02,1784.72 C110.1@-1655.02,1864.76
  PWR w19.68: -1055.75,223.82 -1055.75,458.82 v1(-1012.13,502.44)
  PWR w30: -2149.88,2734.29 -2141.14,2725.55 JP5.1@-2050.04,2725.55 ; -2149.88,4057.4 -2098.98,4108.31 -1948.9,4108.31 ; JP7.1@-2050.04,223.58 -2104.65,223.58 -2149.88,268.82 -2149.88,1908.03 -2020.02,1908.03 -1950.04,1838.05 JP8.2@-1950.04,1825.55 ; JP7.1@-2050.04,225.55 -2022.87,225.55 -2011.14,213.82 -1753.11,213.82 ; J1/J3.21@-1950.04,4025.55 -1950.04,4107.17 -1948.9,4108.31 ; JP2.2@-1760.04,4225.55 -1760.04,4150.87 -1802.6,4108.31 -1948.9,4108.31 ; J13.4@-1750.04,100.55 -1750.04,210.75 -1753.11,213.82 ; J12.4@-1150.04,100.55 -1150.04,221.26 -1152.6,223.82 ; v1(-800.43,223.82) v1(-907.17,223.82) -1055.75,223.82 -1152.6,223.82 ; -1753.11,213.82 v1(-1511.42,213.82) v1(-1401.42,213.82) -1329.37,213.82 TP5.1@-1303.03,240.16 -1286.69,223.82 -1152.6,223.82
  Bottom Signal w11.81: JP2.2@-1760.04,4225.55 -1687.04,4152.55 -585.61,4152.55 -561.53,4176.62 C122.1@-561.53,4204.55 -559.53,4206.55 U10.2@-505.36,4206.55
  Bottom Signal w12: C67.1@-1012.13,576.61 C67.1@-1009.02,579.72
  Bottom Signal w19.68: v1(-1012.13,502.44) C67.1@-1012.13,576.61
  Bottom Signal w30: C115.2@-2156.54,2626.75 -2138.74,2644.55 C116.1@-2109.72,2644.55 -2109.72,2665.87 JP5.1@-2050.04,2725.55 ; JP7.1@-2045.35,220.87 C120.1@-1956.04,220.87 ; C120.1@-1954.88,222.02 C119.2@-1886.04,222.02 v1(-1834.07,222.02)
+5V0_USB: C101.2 C105.2 JP1.1 R7.2 R100.2 U3.1 USB101.A4 USB101.A9 USB101.B4 USB101.B9 | length 1244.6
  Top Signal w11.81: v3@-1890.58,5162.8 -1873.86,5179.53 USB101.A9@-1873.86,5202.13 -1873.86,5238.35 -1864.02,5248.19 USB101.B4@-1864.02,5265.12 ; USB101.B9@-1765.59,5265.12 -1765.59,5232.42 -1775.43,5222.57 USB101.A4@-1775.43,5202.13 -1775.43,5183.23 -1763.71,5171.51 -1737.53,5171.51 v3@-1717.6,5151.57 ; C105.2@-1712.28,5120.55 C105.2@-1710.61,5122.22
  Top Signal w30: JP1.1@-2192.01,4776.99 -2192.01,4948.15 -2153.27,4986.89 R7.2@-2089.53,4986.89 ; R7.2@-2086.34,4988.9 -2086.34,5022.28 -2071.46,5037.17 -1922.95,5037.17 -1905.04,5055.08 R100.2@-1905.04,5125.55 -1905.04,5148 v3@-1890.78,5162.26 ; v3@-1719.04,5152.91 -1719.04,5130.65 C105.2@-1710.61,5122.22 ; C105.2@-1712.28,5120.55 U3.1@-1629.53,5120.55
  GND w30: v3(-1890.94,5161.54) -1890.94,5171.14 -1858.5,5203.58 -1751.65,5203.58 -1719.37,5171.3 v3(-1719.37,5155.24)
+5V0_XDS110: C100.1 JP1.2 JP2.1 R62.1 U101.4 U101.6 | length 2646.3
  Top Signal w11.81: v1(-267.36,5330.47) -267.36,5354.06 R62.1@-262.95,5358.46
  Top Signal w19.68: C100.1@-2191.3,4440.55 -2187.99,4443.86 v3(-2158.46,4443.86) ; U101.6@-2123.43,4392.68 -2146.93,4392.68 -2158.46,4404.21 v3(-2158.46,4443.86) ; U101.4@-2123.43,4443.86 v3(-2158.46,4443.86)
  Top Signal w30: C100.1@-2192.01,4442.76 JP1.2@-2192.01,4582.11
  PWR w39.37: -1834.49,4325.55 JP2.1@-1760.04,4325.55 -1760.04,4422.76
  Bottom Signal w11.81: JP2.1@-1758.9,4335.55 -1758.9,4420.67 -1637.91,4541.65 -1393.39,4541.65 -1235.12,4699.92 -925.67,4699.92 -754.57,4871.02 -399.65,4871.02 -267.36,5003.31 v1(-267.36,5330.47) ; JP2.1@-1750.47,4340.91 JP2.1@-1738.86,4340.91
  other v3: -2152.7,4398.44
ADCINA0/B15/C15/DACA_OUT: J5/J7.70 R12.1 | length 159.1
  Top Signal w5: J5/J7.70@-1950.04,625.55 R12.1@-1790.93,625.55
ADCINA1/B7/D11/DACB_OUT: J1/J3.30 R13.1 | length 209.2
  Top Signal w5: J1/J3.30@-1950.04,3125.55 -1886.04,3061.55 -1886.04,3017.55 -1848.73,2980.24 R13.1@-1826.84,2980.24
ADCINA4/B8: J5/J7.66 R16.1 | length 159.1
  Top Signal w5: J5/J7.66@-1950.04,1025.55 R16.1@-1790.93,1025.55
ADCINA5: J5/J7.65 R17.1 | length 164.4
  Top Signal w5: J5/J7.65@-1946.28,1121.79 J5/J7.65@-1950.04,1125.55 R17.1@-1790.93,1125.55
ADCINA6/D14/E14: J1/J3.23 R18.1 | length 170.5
  Top Signal w5: J1/J3.23@-1946.69,3822.2 R18.1@-1785.63,3822.2
  Top Signal w8: J1/J3.23@-1950.04,3825.55 J1/J3.23@-1946.69,3822.2 ; R18.1@-1785.63,3822.2 R18.1@-1782.28,3818.85
ADCINA7/B30/C3/D12/E30: J1/J3.6 R19.1 | length 295.6
  Bottom Signal w10: J1/J3.6@-2050.04,3525.55 -2002.89,3572.7 -1916.77,3572.7 -1869.63,3525.55 R19.1@-1793.45,3525.55
ADCINA9: J5/J7.46 R20.1 | length 280.2
  Bottom Signal w5: J5/J7.46@-2050.04,1025.55 -1999.04,1076.55 R20.1@-1790.93,1076.55
ADCINA10/B1/C10: J5/J7.64 R21.1 | length 159.1
  Top Signal w5: J5/J7.64@-1950.04,1225.55 R21.1@-1790.93,1225.55
ADCINA11/B10/C0/PGA2_OUT: J1/J3.25 R22.1 | length 194.5
  Top Signal w5: J1/J3.25@-1950.04,3625.55 -1890.19,3625.55 -1829.56,3564.92 R22.1@-1786.25,3564.92 R22.1@-1788.24,3566.91
  Top Signal w10: J1/J3.25@-1950.04,3625.55 J1/J3.25@-1948.05,3623.56
ADCINA12/C5: J5/J7.69 R23.1 | length 159.1
  Top Signal w5: J5/J7.69@-1950.04,725.55 R23.1@-1790.93,725.55
ADCINA14/B14/C4/PGA1_OUT: J1/J3.26 R24.1 | length 369.4
  Top Signal w5: J1/J3.26@-1950.04,3525.55 -1998.74,3574.25 -1998.74,3645.85 -1971.96,3672.63 -1901.09,3672.63 -1891.4,3662.93 R24.1@-1784.93,3662.93
ADCINB0/C11: J5/J7.63 R109.1 | length 159.1
  Top Signal w5.91: J5/J7.63@-1950.04,1325.55 R109.1@-1790.93,1325.55
ADCINB2/C6/E12: J1/J3.24 R25.1 | length 168.3
  Top Signal w5: J1/J3.24@-1949.72,3725.87 R25.1@-1782.35,3725.87
  Top Signal w10: J1/J3.24@-1950.04,3725.55 J1/J3.24@-1949.72,3725.87 ; R25.1@-1782.35,3725.87 R25.1@-1782.04,3726.18
ADCINB4/C8: J5/J7.67 R27.1 | length 159.1
  Top Signal w5: J5/J7.67@-1950.04,925.55 R27.1@-1790.93,925.55
ADCINB5/D15/E15/PGA3_OUT: J5/J7.68 R84.1 | length 159.1
  Top Signal w5: J5/J7.68@-1950.04,825.55 R84.1@-1790.93,825.55
ADCINC14: J5/J7.42 R110.1 | length 425.9
  Bottom Signal w5.91: J5/J7.42@-2050.04,1425.55 -2002.04,1377.55 -1717.18,1377.55 R110.1@-1665.43,1429.3
ADCINPGA1_IN_N: R15.1 U17.6 | length 83.9
  Bottom Signal w5.91: R15.1@-1723.02,3256.11 R15.1@-1731.26,3264.35 -1731.26,3260.41 -1713.8,3242.95 U17.6@-1713.8,3199.32
ADCINPGA1_IN_P: R14.1 U17.4 | length 71.2
  Bottom Signal w5.91: R14.1@-1779.76,3264.35 -1779.76,3260.41 -1764.98,3245.64 U17.4@-1764.98,3199.32
ADCINPGA2_IN_N: R86.1 U17.9 | length 60
  Bottom Signal w5.91: U17.9@-1637.03,3199.32 R86.1@-1637.03,3255.48 ; R86.1@-1637.03,3260.48 R86.1@-1634.34,3263.17
ADCINPGA2_IN_P: R26.1 U17.7 | length 66.1
  Bottom Signal w5.91: U17.7@-1688.21,3199.32 R26.1@-1688.21,3253.33 ; R26.1@-1688.21,3258.33 R26.1@-1682.46,3264.09 R26.1@-1682.46,3260.15
ADCINPGA3_IN_N: R85.1 U17.12 | length 71.8
  Bottom Signal w5.91: U17.12@-1560.26,3199.32 -1560.26,3219.99 -1546.55,3233.7 -1546.55,3252.92 R85.1@-1537.7,3261.78
ADCINPGA3_IN_P: R87.1 U17.10 | length 82.7
  Bottom Signal w5.91: U17.10@-1605.54,3205.23 U17.10@-1611.44,3199.32 -1611.44,3233.98 -1586.18,3259.24 R87.1@-1586.18,3263.17
DEBUG_ID4: R58.1 U2.63 | length 177.9
  Top Signal w5: U2.63@-371.5,4747.4 -371.5,4604.96 -351.26,4584.72 R58.1@-344.37,4584.72
DEBUG_ID5: R59.1 U2.62 | length 245.1
  Top Signal w5: U2.62@-387.24,4747.4 -387.24,4552.48 -369.49,4534.72 R59.1@-344.37,4534.72
DEBUG_ID6: R60.1 U2.61 | length 302.5
  Top Signal w5: U2.61@-402.99,4747.4 -402.99,4516.73 -370.98,4484.72 R60.1@-344.37,4484.72
DEBUG_ID7: R61.1 U2.60 | length 361.8
  Top Signal w5: U2.60@-418.74,4747.4 -418.74,4477.83 -375.63,4434.72 R61.1@-344.37,4434.72
EQEP1A: C68.1 J12.1 R72.1 U13.21 | length 558.2
  Top Signal w7.87: U13.21@-1089.33,460.71 -1089.33,418.35 -1060.47,389.49 -891.57,389.49 -850.04,347.95 J12.1@-850.04,100.55
EQEP1B: C69.1 J12.2 R73.1 U13.20 | length 488.2
  Top Signal w7.87: U13.20@-1114.92,460.71 -1114.92,406.89 -1078.7,370.67 -976.65,370.67 -950.04,344.06 J12.2@-950.04,100.55
EQEP1I: C70.1 J12.3 R74.1 U13.19 | length 397.6
  Top Signal w7.87: U13.19@-1140.51,460.71 -1140.51,395.43 -1064.37,319.29 -1064.37,179.61 -1050.04,165.28 J12.3@-1050.04,100.55
EQEP3A: C71.1 J13.1 R75.1 U13.18 | length 595.2
  Top Signal w7.87: J13.1@-1450.04,100.55 -1450.04,333.23 -1420.24,363.03 -1219.84,363.03 -1166.1,416.77 U13.18@-1166.1,460.71
EQEP3B: C72.1 J13.2 R76.1 U13.17 | length 697.2
  Top Signal w7.87: J13.2@-1540.67,97.13 -1558.11,114.57 -1558.11,354.29 -1523.94,388.46 -1225.79,388.46 -1191.69,422.56 U13.17@-1191.69,460.71
EQEP3I: C73.1 J13.3 R77.1 U13.16 | length 785.2
  Top Signal w7.87: J13.3@-1650.04,100.55 -1650.04,185.08 -1668.43,203.46 -1668.43,369.96 -1627.87,410.51 -1234.33,410.51 -1217.28,427.56 U13.16@-1217.28,460.71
